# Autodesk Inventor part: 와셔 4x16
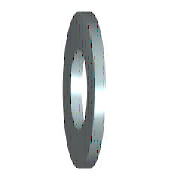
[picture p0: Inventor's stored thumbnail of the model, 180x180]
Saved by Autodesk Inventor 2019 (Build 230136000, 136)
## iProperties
IsCustomPart: 1
Created: 2012-02
Part Number: 와셔 4x16
Material: 강철, 연강
Description: 미터법 평면 와셔
Document SubType Name: Modeling
Standard: ANSI B18.22M
Designer: mduedu
Standard Revision: 1999
Standards Organization: ANSI
Language: ko-KR
Size Designation: 4 W
Categories: <MemberInstance><Categories><Category DisplayName="조임쇠" InternalName="e4da775c-781d-43d5-af7c-5136215cf5a6" Mnemonic="FSTN"><Category DisplayName="와셔" InternalN
Density: 1 g/cm^3
Appearance: 파란색 - 벽 페인트 - 광택
Author: mduedu
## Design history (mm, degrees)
sketch "스케치"
  geometry: C1 r 8 at (0, 0); C2 r 2.35 at (0, 0); 1 further point
  constraints: 2 centre point, 2 coincident
  dimensions: "d0" = 4.7 diameter of C2 (= SD1); "d1" = 16 diameter of C1 (= SD2)
extrude "본체" new body sketch "스케치" distance "d2" = 2.3 (= SD); taper "d3" = 0 deg
workaxis "Work Axis1"
workplane "Work Plane1"
body "Solid1"
other parameters: "SD1" = 4.7 [user parameter; used in 1 equation term], "SD2" = 16 [user parameter; used in 1 equation term], "SD" = 2.3 [user parameter; used in 1 equation term], "d4" = 0, "d5" = 0, "d6" = 0, "d7" = 0, "NND" = 4 [user parameter]
